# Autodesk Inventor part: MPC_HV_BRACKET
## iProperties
Shininess: 64.0
Length Units: 11269
Angle Units: 11279
Time Units: 11290
Mass Units: 11283
Length Display Precision: 3
Angle Display Precision: 2
Compacted: True
Part Number: MPC_HV_BRACKET
Document SubType Name: Modeling
Created: 2004-08
Designer: John Blackburn
Manufacturer: Standard
Standards Organization: Custom
Material: Aluminum-6061
Density: 0.0
Volumn: 0.0
Area: 0.0
PropertySet Name: Model Information
Control State: 0
Master: False
Checked Out: False
Author: John Blackburn
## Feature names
1. Extrusion1
2. Chamfer1
3. Extrusion2
